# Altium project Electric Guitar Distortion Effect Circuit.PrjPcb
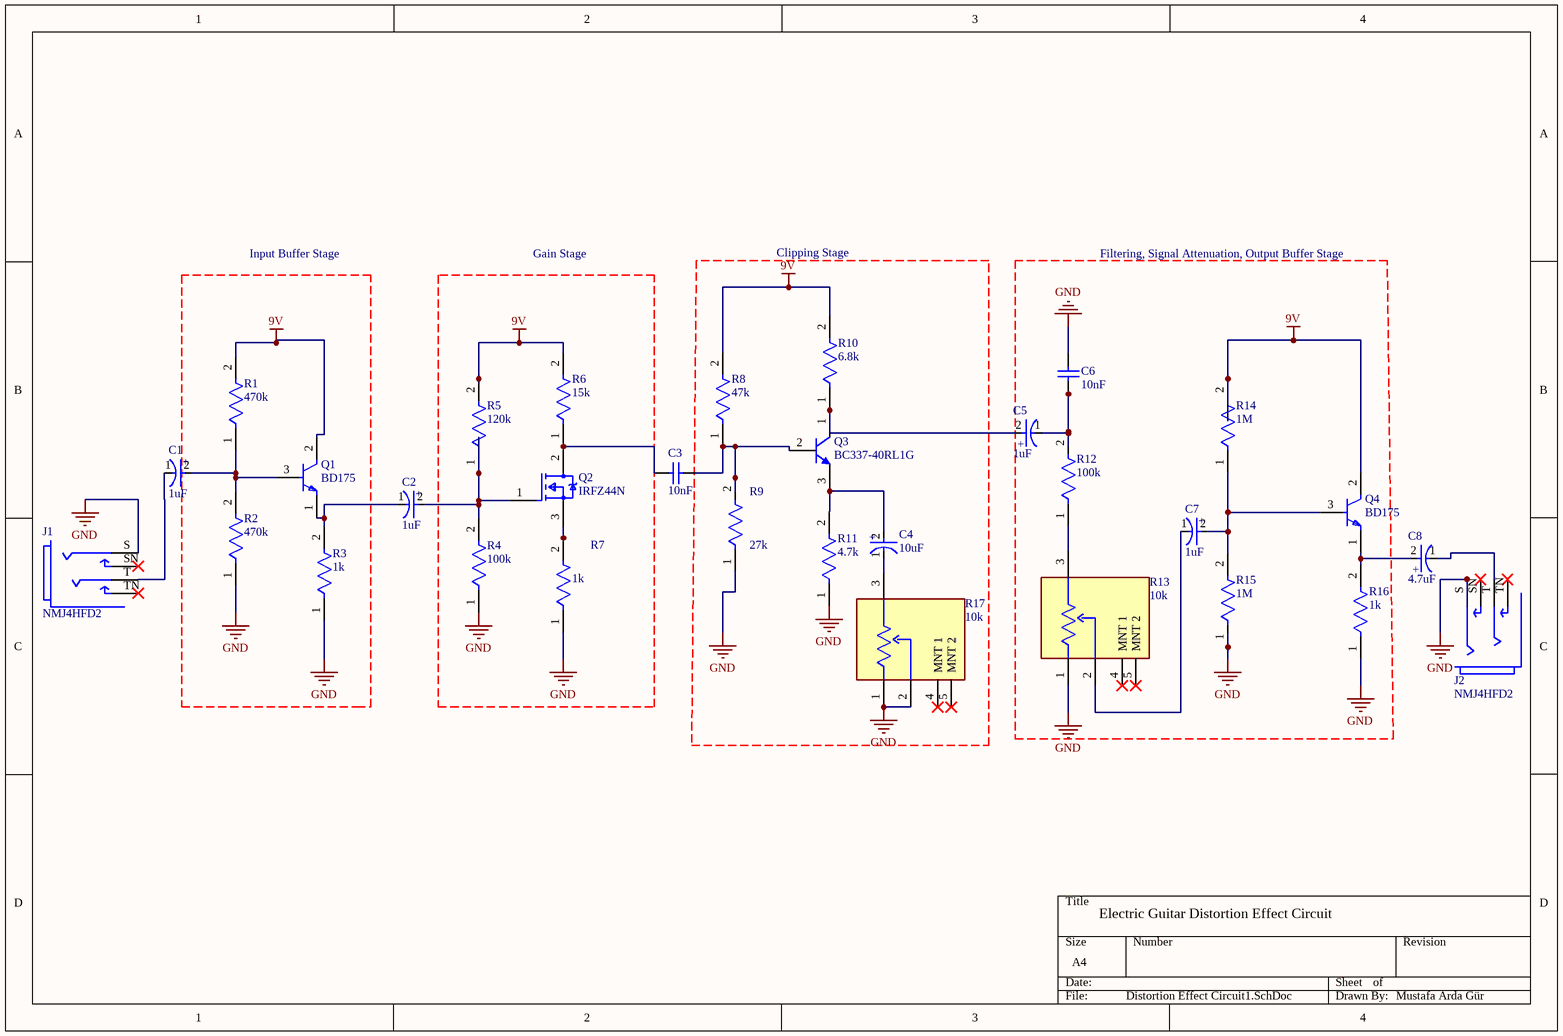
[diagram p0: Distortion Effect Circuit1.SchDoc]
CAGE_CODE: ?????; CONTRACT_NUMBER: <CONTRACT NO>; DOC_NO_ASSY_DWG: <ASSY DWG NO>; DOC_NO_BOM: <BOM DOC NO>; DOC_NO_FAB_DWG: <FAB DWG NO>; DOC_NO_SCH_DWG: <SCH DWG NO>; PCB_2_DEC_TOL: +/-.01; PCB_3_DEC_TOL: +/-.010; PCB_ANG_TOL: +/-1/2; PCB_ASSEMBLY_NO: <PCB ASSY NO>; PCB_CHECKER: - -----; PCB_CHECKER_APP_DATE: --/--/----; PCB_DESIGNER: - -----; PCB_DESIGNER_APP_DATE: --/--/----; PCB_DWG_NO: <PCB DWG NO>; PCB_ENGINEER: - -----; PCB_ENGINEER_APP_DATE: --/--/----; PCB_PART_NUMBER: <PCB PN>; PCB_REV: A; SCH_REV: A
1 sheet, 31 parts. Net scope: global (net labels, ports and power ports of the same name join across sheets).
Board file: PcbDoc Electric Guitar Distortion Effect Circuit.PcbDoc

## Sheet Distortion Effect Circuit1.SchDoc: Electric Guitar Distortion Effect Circuit Design
size A4; DrawnBy: Mustafa Arda Gür; Revision: 1.0; SheetNumber: 1; SheetTotal: 1

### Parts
C1  1uF  [FP-RAD-TH-D_5_0_5-L_11_1-MFG]
C2  1uF  [FP-RAD-TH-D_5_0_5-L_11_1-MFG]
C3  10nF  [KEMT-C315-THT-2]
C4  10uF  [FP-RAD-TH-D_5_0_5-L_11_1-MFG]
C5  1uF  [FP-RAD-TH-D_5_0_5-L_11_1-MFG]
C6  10nF  [KEMT-C315-THT-2]
C7  1uF  [FP-RAD-TH-D_5_0_5-L_11_1-MFG]
C8  4.7uF  [FP-RAD-TH-D_5_0_5-L_11_1-MFG]
J1  NMJ4HFD2  [FP-NMJ4HFD2-MFG]
J2  NMJ4HFD2  [FP-NMJ4HFD2-MFG]
Q1  BD175  [FP-340AS-MFG]
Q2  IRFZ44N  [FP-TO-220AB-MFG]
Q3  BC337-40RL1G  [ONSC-TO-92-3-29-11_AM_BL]
Q4  BD175  [FP-340AS-MFG]
R1  470k  [FP-CRGP0805-IPC_C]
R2  470k  [FP-CRGP0805-IPC_C]
R3  1k  [FP-CRGP0805-IPC_C]
R4  100k  [FP-CRGP0805-IPC_C]
R5  120k  [FP-CRGP0805-IPC_C]
R6  15k  [FP-CRGP0805-IPC_C]
R7  1k  [FP-CRGP0805-IPC_C]
R8  47k  [FP-CRGP0805-IPC_C]
R9  27k  [FP-CRGP0805-IPC_C]
R10  6.8k  [FP-CRGP0805-IPC_C]
R11  4.7k  [FP-CRGP0805-IPC_C]
R12  100k  [FP-CRGP0805-IPC_C]
R13  10k  [FP-RK09L1140A2U-MFG]
R14  1M  [FP-CRGP0805-IPC_C]
R15  1M  [FP-CRGP0805-IPC_C]
R16  1k  [FP-CRGP0805-IPC_C]
R17  10k  [FP-RK09L1140A2U-MFG]

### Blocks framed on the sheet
Input Buffer Stage: Q1 R1-R3
Gain Stage: Q2 R4-R7
Clipping Stage: C4 Q3 R8-R11 R17
Filtering, Signal Attenuation, Output Buffer Stage: C5-C7 Q4 R12-R16

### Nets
9V: Q1.2(C) Q4.2(C) R1.2 R5.2 R6.2 R8.2 R10.2 R14.2
GND: C6.1 J1.S J2.S R2.1 R3.1 R4.1 R7.1 R9.1 R11.1 R13.1 R15.1 R16.1 R17.1 R17.2
NetC1_1: C1.1(C) J1.T
NetC1_2: C1.2(A) Q1.3(B) R1.1 R2.2
NetC2_1: C2.1(C) Q1.1(E) R3.2
NetC2_2: C2.2(A) Q2.1(GATE) R4.2 R5.1
NetC3_1: C3.1 Q2.2(DRAIN) R6.1
NetC3_2: C3.2 Q3.2(B) R8.1 R9.2
NetC4_1: C4.1(C) R17.3
NetC4_2: C4.2(A) Q3.3(E) R11.2
NetC5_1: C5.1(C) C6.2 R12.2
NetC5_2: C5.2(A) Q3.1(C) R10.1
NetC7_1: C7.1(C) R13.2
NetC7_2: C7.2(A) Q4.3(B) R14.1 R15.2
NetC8_1: C8.1(C) J2.T
NetC8_2: C8.2(A) Q4.1(E) R16.2
NetQ2_3: Q2.3(SOURCE) R7.2
NetR12_1: R12.1 R13.3

Not connected (* = marked no-connect by the designer): J1 SN* TN*; J2 SN* TN*; R13 4(MNT_1)* 5(MNT_2)*; R17 4(MNT_1)* 5(MNT_2)*

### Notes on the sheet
- Electric Guitar Distortion Effect Circuit
- Mustafa Arda Gür

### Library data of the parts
C1 C2 C5 C7 = CMP-05427-001266-1: Aluminum Electrolytic Capacitors (Radial Lead Type) 1uF ±20% 50V; Ripple Current: 8mA; Life (Hours): 5000Hour; Lead Diameter: 0.5mm
C3 C6 = CMP-1664-00007-1: Capacitor, Ceramic, 0.01 uF, +/- 10%, 100 V, X7R, -55 to 125 degC, 2-Pin THD, RoHS, Bulk; Output Voltage: 70 V; Case\Package: PDIP; Forward Current: 60 mA; Nominal Vf: 1.3 V; Forward Voltage: 1.5 V; Channels: 2; Max Power Dissipation: 400 mW; Vce Max: 500 mV
C4 = CMP-05427-000246-1: Aluminum Electrolytic Capacitors (Radial Lead Type) 10uF ±20% 50V
C8 = CMP-05427-000256-1: Aluminum Electrolytic Capacitors (Radial Lead Type) AEC-Q200 Qualified 4.7uF ±20% 50V; Polarity: Polar; Lead Diameter: 0.5mm; Life (Hours): 1000Hour; Impedance: 1.3R; Ripple Current: 95mA
J1 J2 = CMP-78736-000001-1: Conn 1/4" Mono Jack F 3 POS Solder RA Thru-Hole 3 Terminal 1 Port; Manufacturer: Neutrik; Number Of Contacts: 2; Current Rating: 0.5A; Voltage Rating: 50V; Conn Orientation: Horizontal; Is Female: yes
Q1 Q4 = CMP-013-00036-1: npn; Frequency: 15MHz
Q2 = CMP-013-00037-1
Q3 = CMP-1048-01582-1: Amplifier Transistor, NPN Silicon, 3-Pin TO-92, Pb-Free, Tape and Reel; Manufacturer: On Semiconductor; IC Continuous (A): 0.8
R1-R12 R14-R16 = CMP-03211-007232-1: CRGP0805 470KΩ 0.33W ±100ppm/°C 1% 150V; Manufacturer: TE; Manufacturer Part Number: CRGP0805F470K; Tolerance: 0.01
R13 R17 = CMP-24118-000002-1: 9mm Size Metal Shaft Snap-in Type RK09L Series; Manufacturer Part Number: RK09L1140A2U; Manufacturer: ALPS; Tolerance: 20%; Resistance: 10kΩ; Standoff Height: 2.55mm; Value: 10kΩ; Power Rating: 0.05W; Voltage Rating: 50V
